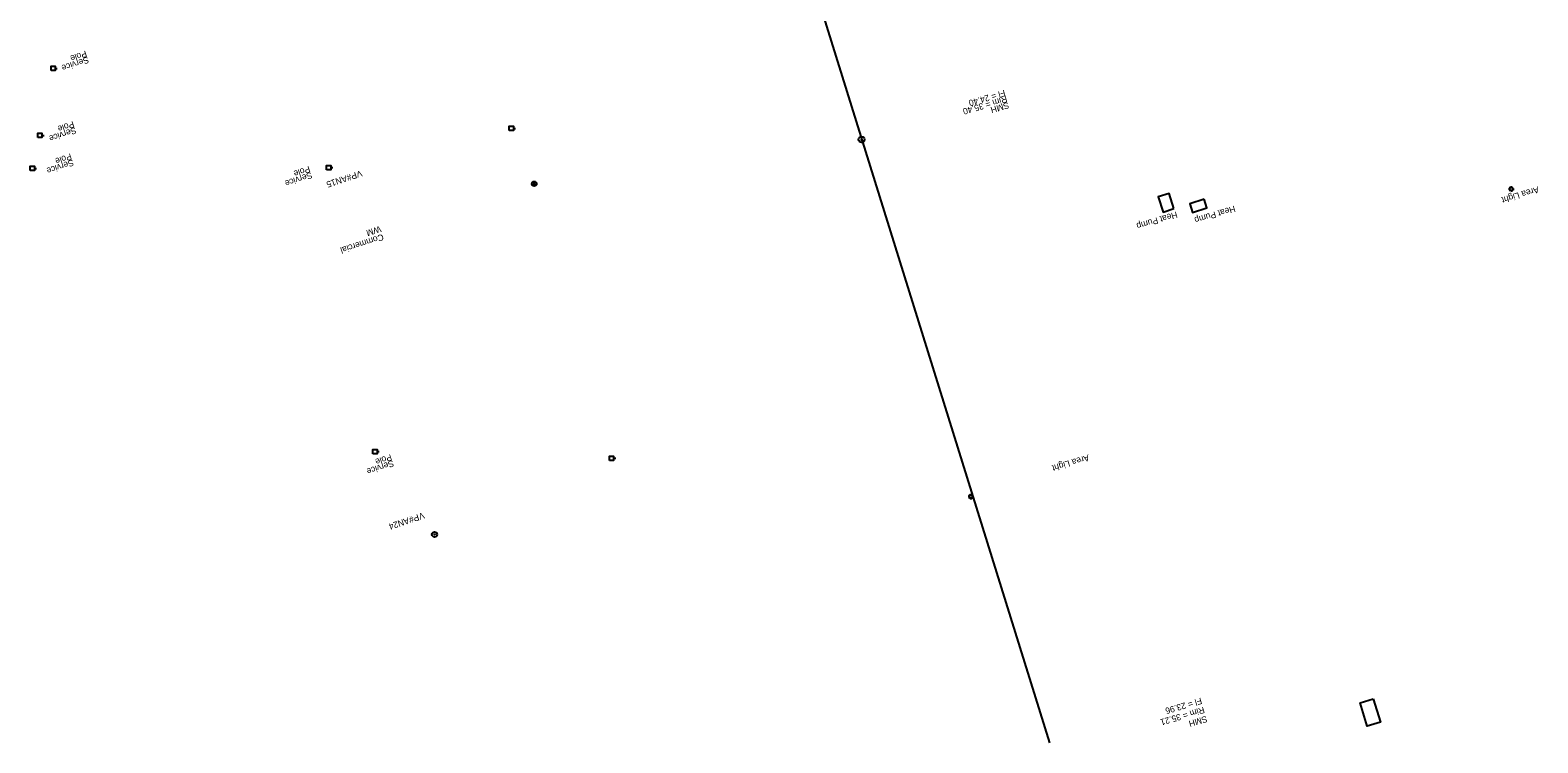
# Model space of a CAD drawing. Extents: x 3872070 to 3879223, y 293944 to 310567.
# Drawn here: x 3875962 to 3876679, y 301287 to 301626 of the extents above; entities that cross this region are included whole.
import ezdxf

# ---------------------------------------------------------------- set-up
doc = ezdxf.new("R2010")
doc.units = 0
for name, color, linetype in [('Level 3', 7, 'Continuous'), ('Level 33', 7, 'Continuous'), ('Level 34', 7, 'Continuous'), ('Level 35', 7, 'Continuous'), ('Level 4', 7, 'Continuous'), ('Level 5', 7, 'Continuous')]:
    doc.layers.add(name, color=color, linetype=linetype)

msp = doc.modelspace()

# ---------------------------------------------------------------- linework, layer by layer
at = {"layer": 'Level 3'}
msp.add_line((3876447.11, 301287.36), (3876271.58, 301851.5), dxfattribs=at)
msp.add_circle((3876357.45, 301574.46), 1.41, dxfattribs=at)
at = {"layer": 'Level 4'}
for p, q in [((3875973.64, 301608.29), (3875974.64, 301608.29)), ((3875967.33, 301576.4), (3875968.33, 301576.4)), ((3876191.71, 301579.75), (3876192.71, 301579.75)), ((3875963.71, 301560.73), (3875964.71, 301560.73)), ((3876104.83, 301561.08), (3876105.83, 301561.08)), ((3876666.21, 301551.4), (3876665.81, 301551.8)), ((3876666.73, 301551.61), (3876666.73, 301552.19)), ((3876667.24, 301551.4), (3876667.65, 301551.8)), ((3876666, 301550.89), (3876665.43, 301550.89)), ((3876665.81, 301549.97), (3876666.21, 301550.37)), ((3876666.73, 301550.16), (3876666.73, 301549.59)), ((3876667.65, 301549.97), (3876667.24, 301550.37)), ((3876667.45, 301550.89), (3876668.03, 301550.89)), ((3876126.87, 301425.94), (3876127.87, 301425.94)), ((3876239.43, 301422.76), (3876240.43, 301422.76)), ((3876408.75, 301404.5), (3876408.18, 301404.5)), ((3876408.96, 301405.01), (3876408.56, 301405.41)), ((3876408.56, 301403.58), (3876408.96, 301403.98)), ((3876409.48, 301405.22), (3876409.48, 301405.8)), ((3876409.48, 301403.77), (3876409.48, 301403.2)), ((3876409.99, 301405.01), (3876410.4, 301405.41)), ((3876410.4, 301403.58), (3876409.99, 301403.98)), ((3876410.2, 301404.5), (3876410.78, 301404.5))]:
    msp.add_line(p, q, dxfattribs=at)
for points in [[(3875971.64, 301607.29), (3875971.64, 301609.29), (3875973.64, 301609.29), (3875973.64, 301607.29)], [(3876189.71, 301578.75), (3876189.71, 301580.75), (3876191.71, 301580.75), (3876191.71, 301578.75)], [(3875965.33, 301575.4), (3875965.33, 301577.4), (3875967.33, 301577.4), (3875967.33, 301575.4)], [(3875961.71, 301559.73), (3875961.71, 301561.73), (3875963.71, 301561.73), (3875963.71, 301559.73)], [(3876102.83, 301560.08), (3876102.83, 301562.08), (3876104.83, 301562.08), (3876104.83, 301560.08)], [(3876124.87, 301424.94), (3876124.87, 301426.94), (3876126.87, 301426.94), (3876126.87, 301424.94)], [(3876237.43, 301421.76), (3876237.43, 301423.76), (3876239.43, 301423.76), (3876239.43, 301421.76)]]:
    msp.add_lwpolyline(points, close=True, dxfattribs=at)
for points in [[(3876506.1, 301541.58), (3876503.82, 301548.82), (3876498.66, 301547.2), (3876500.94, 301539.95), (3876506.1, 301541.58)], [(3876520.47, 301546.13), (3876513.62, 301543.91), (3876514.97, 301539.72), (3876521.83, 301541.94), (3876520.47, 301546.13)], [(3876601, 301308.29), (3876604.41, 301297.21), (3876598.17, 301295.29), (3876594.75, 301306.37), (3876601, 301308.29)]]:
    msp.add_lwpolyline(points, dxfattribs=at)
for centre, radius in [((3876666.73, 301550.89), 0.725), ((3876409.48, 301404.5), 0.725), ((3876154.19, 301386.51), 1.22), ((3876154.19, 301386.51), 0.0992), ((3876154.19, 301386.51), 0.0483)]:
    msp.add_circle(centre, radius, dxfattribs=at)
at = {"layer": 'Level 5'}
for p in [(3876200.83, 301554.17), (3876200.83, 301552.58), (3876202.42, 301554.17), (3876202.42, 301552.58)]:
    msp.add_line(p, (3876201.62, 301553.38), dxfattribs=at)
msp.add_circle((3876201.62, 301553.38), 1.12, dxfattribs=at)

# ---------------------------------------------------------------- texts
at = {"layer": 'Level 3'}
msp.add_text('S', height=1.41, rotation=279.01833, dxfattribs=at).set_placement((3876356.67, 301574.82))
at = {"layer": 'Level 33'}
for s, p in [('Rim = 35.40', (3876426.25, 301595.22)), ('Fl = 24.40', (3876425.4, 301598.12)), ('SMH', (3876427.1, 301592.31)), ('Fl = 23.96', (3876518.94, 301308.88)), ('Rim = 35.21', (3876520.2, 301304.56)), ('SMH', (3876521.46, 301300.25))]:
    msp.add_text(s, height=3, rotation=196.31202, dxfattribs=at).set_placement(p)
at = {"layer": 'Level 34'}
for s, rotation, p in [('Pole', 198.45225, (3875988.11, 301616.79)), ('Service', 198.45225, (3875989.06, 301613.92)), ('Pole', 198.45225, (3875982.11, 301583.23)), ('Service', 198.45225, (3875983.07, 301580.36)), ('Pole', 198.45225, (3875980.91, 301567.88)), ('Service', 198.45225, (3875981.87, 301565.01)), ('Service', 198.45225, (3876095.36, 301559.02)), ('Pole', 198.45225, (3876094.4, 301561.89)), ('VP#AN15', 198.45225, (3876119.15, 301559.9)), ('Area Light', 196.76106, (3876679.34, 301552.15)), ('Heat Pump', 196.45376, (3876507.27, 301540.2)), ('Heat Pump', 196.45376, (3876534.85, 301543.02)), ('Pole', 198.45225, (3876133.28, 301424.8)), ('Area Light', 196.76106, (3876465.32, 301424.6)), ('Service', 198.45225, (3876134.23, 301421.93)), ('VP#AN24', 198.45225, (3876148.79, 301397.1))]:
    msp.add_text(s, height=3, rotation=rotation, dxfattribs=at).set_placement(p)
at = {"layer": 'Level 35'}
for s, p in [('WM', (3876128.18, 301533.41)), ('Commercial', (3876129.41, 301529.6))]:
    msp.add_text(s, height=3, rotation=198.02024, dxfattribs=at).set_placement(p)

doc.saveas('drawing.dxf')
